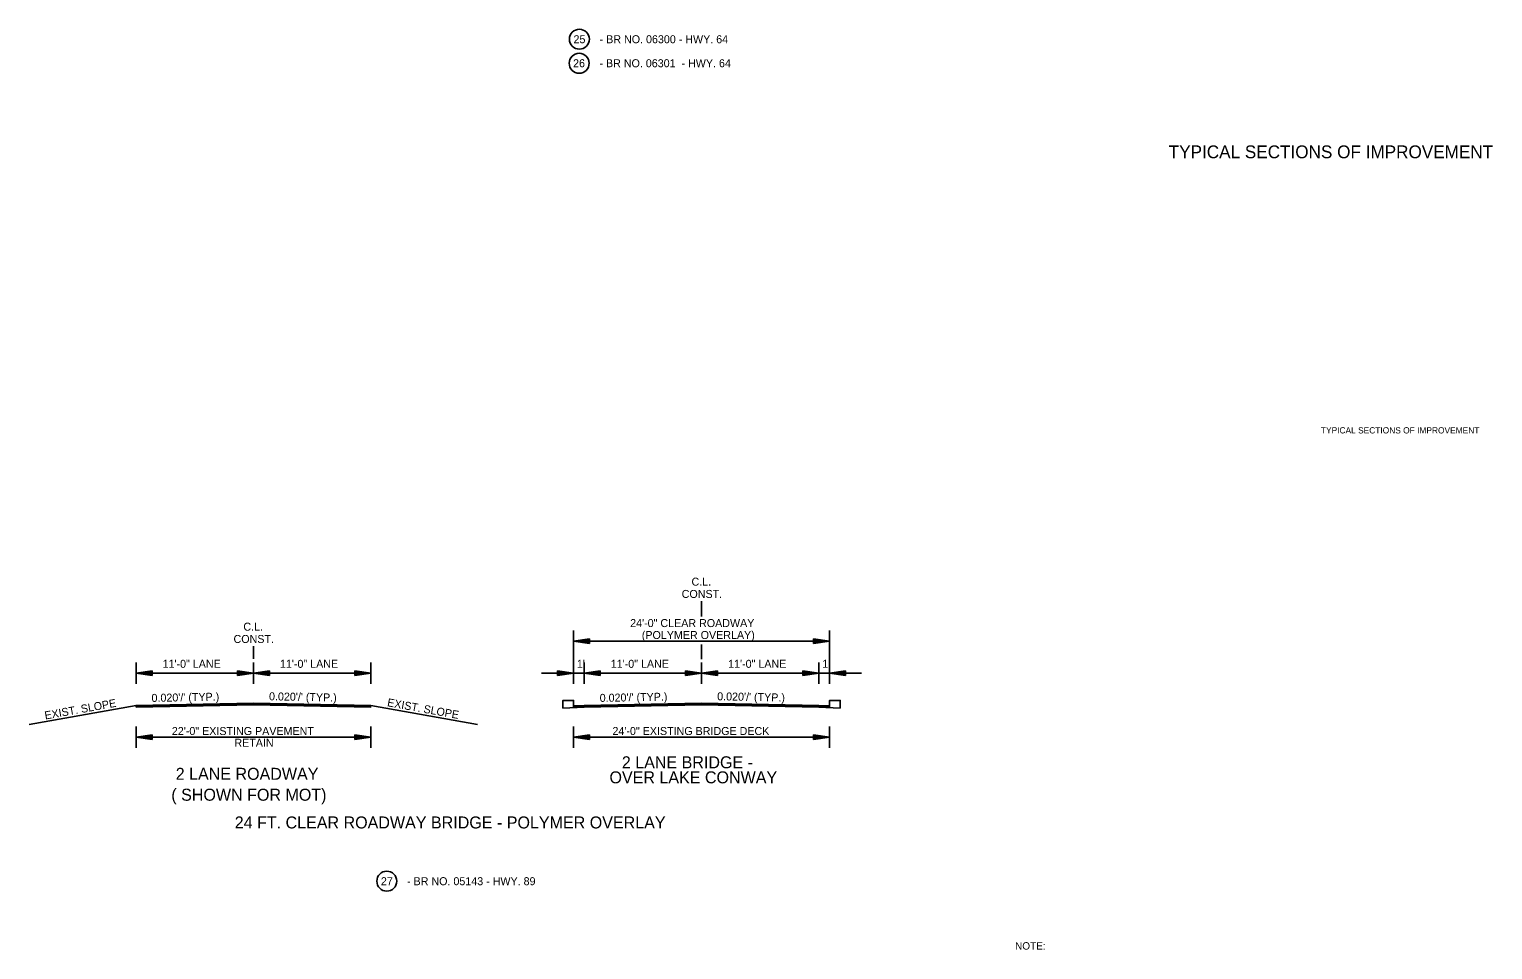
# Model space of a CAD drawing. Extents: x 550980 to 1930787, y -1972975 to 596640.
# Drawn here: x 551174 to 552546, y -1958674 to -1957811 of the extents above; entities that cross this region are included whole.
import ezdxf

# ---------------------------------------------------------------- set-up
doc = ezdxf.new("R2010")
doc.units = 0
for name, color, linetype in [('R_Border', 7, 'Continuous'), ('R_Border Notes', 7, 'Continuous'), ('R_Draft', 7, 'Continuous'), ('S_AREA_CALC', 7, 'Continuous')]:
    doc.layers.add(name, color=color, linetype=linetype)

# ---------------------------------------------------------------- blocks, each defined once
blk = doc.blocks.new('BPPOLY')
at = {"layer": 'R_Border'}
blk.add_circle((0, 0), 9.34, dxfattribs=at)
blk = doc.blocks.new('ARROW')
at = {"layer": 'R_Draft'}
for p, q in [((-2, 0.3), (0, 0)), ((-2, 0.3), (-2, -0.3)), ((-2, 0.25), (-0.334, 0)), ((-2, 0.199), (-0.678, 0)), ((-2, 0.149), (-1.011, 0)), ((-2, 0.097), (-1.35, 0)), ((-2, 0.047), (-1.684, 0)), ((-2, -0.3), (0, 0)), ((-2, -0.098), (-1.35, 0)), ((-2, -0.199), (-0.678, 0)), ((-2, -0.25), (-0.334, 0)), ((-2, -0.149), (-1.011, 0)), ((-2, -0.047), (-1.684, 0))]:
    blk.add_line(p, q, dxfattribs=at)

msp = doc.modelspace()

# ---------------------------------------------------------------- linework, layer by layer
at = {"layer": 'R_Border'}
for p, q in [((551804.5, -1958347.3), (551804.5, -1958361.8)), ((551684.5, -1958374.8), (551684.5, -1958424.8)), ((551924.5, -1958374.8), (551924.5, -1958424.8)), ((551384.5, -1958389.5), (551384.5, -1958401.5)), ((551684.5, -1958384.8), (551924.5, -1958384.8)), ((551804.5, -1958387.8), (551804.5, -1958401.8)), ((551274.5, -1958404.8), (551274.5, -1958424.8)), ((551384.5, -1958404.8), (551384.5, -1958424.8)), ((551494.5, -1958404.8), (551494.5, -1958424.8)), ((551694.5, -1958404.8), (551694.5, -1958424.8)), ((551804.5, -1958404.8), (551804.5, -1958424.8)), ((551914.5, -1958404.8), (551914.5, -1958424.8)), ((551274.5, -1958414.8), (551494.5, -1958414.8)), ((551654.5, -1958414.8), (551954.5, -1958414.8)), ((551274.5, -1958445), (551174.5, -1958463)), ((551494.5, -1958445), (551594.5, -1958463)), ((551274.5, -1958464.8), (551274.5, -1958484.8)), ((551274.5, -1958474.8), (551494.5, -1958474.8)), ((551494.5, -1958464.8), (551494.5, -1958484.8)), ((551684.5, -1958464.8), (551684.5, -1958484.8)), ((551684.5, -1958474.8), (551924.5, -1958474.8)), ((551924.5, -1958464.8), (551924.5, -1958484.8))]:
    msp.add_line(p, q, dxfattribs=at)
for points in [[(551274.5, -1958445), (551274.5, -1958445), (551384.5, -1958442.8), (551494.5, -1958445), (551494.5, -1958445)], [(551274.5, -1958445.3), (551274.5, -1958445.3), (551384.5, -1958443.1), (551494.5, -1958445.3), (551494.5, -1958445.3)], [(551274.5, -1958445.6), (551274.5, -1958445.6), (551384.5, -1958443.4), (551494.5, -1958445.6), (551494.5, -1958445.6)], [(551274.5, -1958445.9), (551274.5, -1958445.9), (551384.5, -1958443.7), (551494.5, -1958445.9), (551494.5, -1958445.9)], [(551274.5, -1958446.2), (551274.5, -1958446.2), (551384.5, -1958444), (551494.5, -1958446.2), (551494.5, -1958446.2)], [(551274.5, -1958446.5), (551274.5, -1958446.5), (551384.5, -1958444.3), (551494.5, -1958446.5), (551494.5, -1958446.5)], [(551274.5, -1958446.8), (551274.5, -1958446.8), (551384.5, -1958444.6), (551494.5, -1958446.8), (551494.5, -1958446.8)], [(551684.5, -1958446.9), (551684.5, -1958440.4), (551674.5, -1958440.4), (551674.5, -1958447.6)], [(551674.5, -1958447.6), (551694.5, -1958446.8), (551804.5, -1958444.6), (551914.5, -1958446.8), (551934.5, -1958447.6)], [(551684.5, -1958445.4), (551694.5, -1958445), (551804.5, -1958442.8), (551914.5, -1958445), (551924.5, -1958445.4)], [(551684.5, -1958445.7), (551694.5, -1958445.3), (551804.5, -1958443.1), (551914.5, -1958445.3), (551924.5, -1958445.7)], [(551684.5, -1958446), (551694.5, -1958445.6), (551804.5, -1958443.4), (551914.5, -1958445.6), (551924.5, -1958446)], [(551684.5, -1958446.3), (551694.5, -1958445.9), (551804.5, -1958443.7), (551914.5, -1958445.9), (551924.5, -1958446.3)], [(551684.5, -1958446.6), (551694.5, -1958446.2), (551804.5, -1958444), (551914.5, -1958446.2), (551924.5, -1958446.6)], [(551684.5, -1958446.9), (551694.5, -1958446.5), (551804.5, -1958444.3), (551914.5, -1958446.5), (551924.5, -1958446.9)], [(551924.5, -1958447.6), (551924.5, -1958440.4), (551934.5, -1958440.4), (551934.5, -1958447.6)]]:
    msp.add_lwpolyline(points, dxfattribs=at)

# ---------------------------------------------------------------- block references
for p in [(551690, -1957820.5), (551689.8, -1957843.1), (551509.5, -1958609.8)]:
    msp.add_blockref('BPPOLY', p, dxfattribs=at)
at = {"layer": 'R_Border', "xscale": 7.5, "yscale": 7.5, "rotation": 180}
for p in [(551684.5, -1958384.8), (551274.5, -1958414.8), (551384.5, -1958414.8), (551694.5, -1958414.8), (551804.5, -1958414.8), (551924.5, -1958414.8), (551274.5, -1958474.8), (551684.5, -1958474.8)]:
    msp.add_blockref('ARROW', p, dxfattribs=at)
at = {"layer": 'R_Border', "xscale": 7.5, "yscale": 7.5}
for p in [(551924.5, -1958384.8), (551384.5, -1958414.8), (551494.5, -1958414.8), (551684.5, -1958414.8), (551804.5, -1958414.8), (551914.5, -1958414.8), (551494.5, -1958474.8), (551924.5, -1958474.8)]:
    msp.add_blockref('ARROW', p, dxfattribs=at)

# ---------------------------------------------------------------- texts
at = {"layer": 'R_Border'}
for s, height, p in [('25 ', 7.5, (551684.5, -1957824.3)), ('- BR NO. 06300 - HWY. 64', 7.5, (551709, -1957824.3)), ('26', 7.5, (551684.1, -1957846.8)), ('- BR NO. 06301  - HWY. 64', 7.5, (551708.8, -1957846.8)), ('C.L.', 7.5, (551795.1, -1958332.8)), ('CONST.', 7.5, (551785.9, -1958344.3)), ('C.L.', 7.5, (551375.1, -1958375)), ('24\'-0" CLEAR ROADWAY', 7.5, (551737.6, -1958371.6)), ('CONST.', 7.5, (551365.9, -1958386.5)), ('(POLYMER OVERLAY)', 7.5, (551748.5, -1958382.8)), ('11\'-0" LANE', 7.5, (551299.4, -1958409.8)), ('11\'-0" LANE', 7.5, (551409.4, -1958409.8)), ("1'", 7.5, (551687.6, -1958409.8)), ('11\'-0" LANE', 7.5, (551719.4, -1958409.8)), ('11\'-0" LANE', 7.5, (551829.4, -1958409.8)), ("1'", 7.5, (551917.6, -1958409.8)), ('22\'-0" EXISTING PAVEMENT', 7.5, (551308.1, -1958472.8)), ('RETAIN', 7.5, (551366.7, -1958483.8)), ('24\'-0" EXISTING BRIDGE DECK', 7.5, (551721, -1958472.8)), ('2 LANE ROADWAY', 11.25, (551311.7, -1958514.8)), ('2 LANE BRIDGE - ', 11.25, (551729.8, -1958504)), ('OVER LAKE CONWAY', 11.25, (551718.2, -1958518.1)), ('( SHOWN FOR MOT)', 11.25, (551307.6, -1958534.4)), ('24 FT. CLEAR ROADWAY BRIDGE - POLYMER OVERLAY', 11.25, (551367, -1958560.4)), ('27', 7.5, (551504, -1958613.6)), ('- BR NO. 05143 - HWY. 89', 7.5, (551528.5, -1958613.6))]:
    msp.add_text(s, height=height, dxfattribs=at).set_placement(p)
for s, height, rotation, p in [('TYPICAL SECTIONS OF IMPROVEMENT', 12, 360, (552242.3, -1957932.1)), ("0.020'/' (TYP.)", 7.5, 1.1458, (551289.1, -1958441.8)), ("0.020'/' (TYP.)", 7.5, 358.8542, (551399.1, -1958440.2)), ("0.020'/' (TYP.)", 7.5, 1.1458, (551709.1, -1958441.8)), ("0.020'/' (TYP.)", 7.5, 358.8542, (551819.1, -1958440.2)), ('EXIST. SLOPE', 7.5, 10.204, (551189.5, -1958458.3)), ('EXIST. SLOPE', 7.5, 349.796, (551509.5, -1958445.7))]:
    msp.add_text(s, height=height, rotation=rotation, dxfattribs=at).set_placement(p)
at = {"layer": 'R_Border Notes'}
msp.add_text('NOTE: ', height=7, dxfattribs=at).set_placement((552098.3, -1958674))
at = {"layer": 'S_AREA_CALC'}
msp.add_text('TYPICAL SECTIONS OF IMPROVEMENT', height=5.862, rotation=360, dxfattribs=at).set_placement((552384.9, -1958190.1))

doc.saveas('drawing.dxf')
